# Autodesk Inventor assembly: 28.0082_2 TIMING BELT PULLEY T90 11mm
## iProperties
Created: 2007-04
Part Number: 28.0082_2 TIMING BELT PULLEY T90 11mm
Document SubType Name: Assembly
Designer: Andy Moles
Author: Andy Moles
